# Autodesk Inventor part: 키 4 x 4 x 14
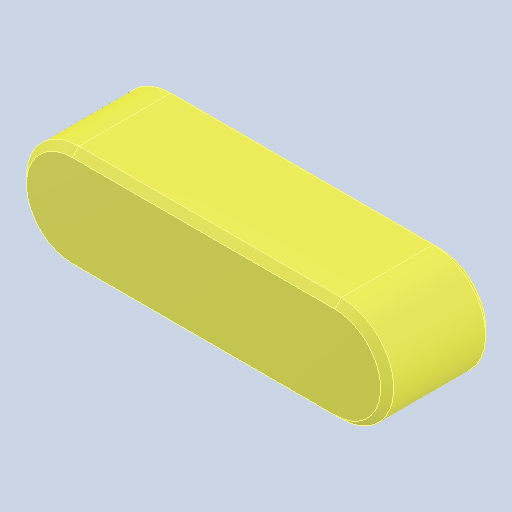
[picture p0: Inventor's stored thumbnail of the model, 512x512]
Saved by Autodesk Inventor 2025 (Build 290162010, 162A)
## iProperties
Created: 2024-07
Part Number: 키 4 x 4 x 14
Material: 강철, 연강
Description: 키 및 해당 키홈
Document SubType Name: Modeling
Designer: 계정
Density: 7.85 g/cm^3
Appearance: 기본값
Author: jhkim
Sending System: Autodesk Inventor 2025
Preprocessor: ST-DEVELOPER v20
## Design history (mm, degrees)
feature "Solid1"
node "솔리드1"
